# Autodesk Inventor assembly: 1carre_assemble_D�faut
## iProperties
Created: 2011-01
Part Number: 1carre_assemble_D�faut
Document SubType Name: Assembly
Designer: eric
Mass: 26.6121 g
Surface Area: 360.583 cm^2
Volume: 26.6121 cm^3
Density: 1 g/cm^3
Author: eric
